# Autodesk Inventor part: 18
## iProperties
Created: 2011-12
Part Number: 18
Document SubType Name: Modeling
Designer: D Cole
Density: 1 g/cm^3
Author: D Cole
Translation Standard: STEP AP214IS
File Name: P:\Fastrack\53972_CRANE 3D\Press Fit\HATTERSLEY\100TH-PF\18MM\18.stp
Preprocessor: Autodesk Inventor 2008
Postprocessor: Build: 342, Release: 2008 SP3 - Date: Tue 05/27/2008
Sent Units: MILLIMETERS
Uncertainty: 0.01
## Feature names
1. Base1
